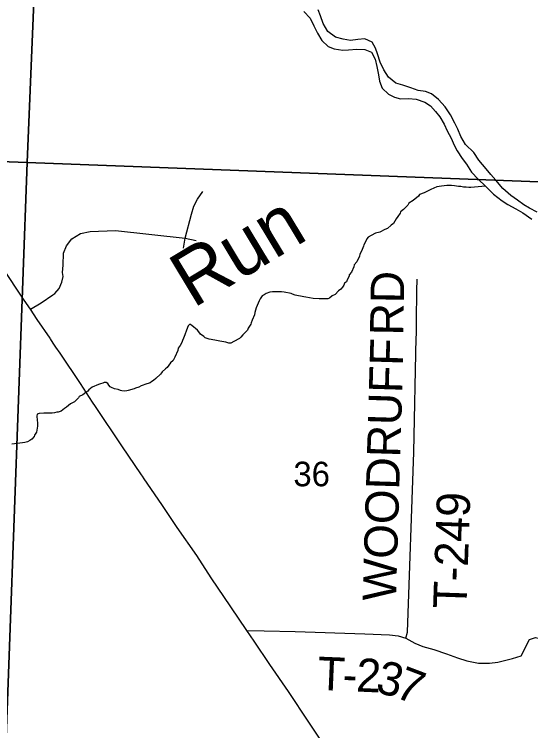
# Model space of a CAD drawing. Extents: x 0 to 34, y 0 to 22.
# Drawn here: x 5.004 to 5.884, y 17.741 to 18.962 of the extents above; entities that cross this region are included whole.
import ezdxf

# ---------------------------------------------------------------- set-up
doc = ezdxf.new("R2010")
doc.units = 0
for name, color, linetype in [('GM_X_Major_River', 7, 'Continuous'), ('GM_X_Minor_River', 7, 'Continuous'), ('GM_X_Minor_River_Text', 7, 'Continuous'), ('GM_X_Section', 7, 'Continuous'), ('GM_X_Section_Text', 7, 'Continuous'), ('GM_X_Township_Road', 7, 'Continuous'), ('GM_X_Township_Road_Text', 7, 'Continuous'), ('GM_X_US_Route', 7, 'Continuous')]:
    doc.layers.add(name, color=color, linetype=linetype)

msp = doc.modelspace()

# ---------------------------------------------------------------- linework, layer by layer
at = {"layer": 'GM_X_Major_River'}
for points in [[(5.4975, 18.9668), (5.5083, 18.9552), (5.5146, 18.9422), (5.5208, 18.9295), (5.5281, 18.9173), (5.5393, 18.9068), (5.5495, 18.9028), (5.5643, 18.901), (5.5738, 18.9013), (5.5882, 18.9025), (5.6015, 18.9019), (5.6132, 18.8971), (5.619, 18.8857), (5.6222, 18.8727), (5.625, 18.8586), (5.6267, 18.8479), (5.6314, 18.8361), (5.6422, 18.826), (5.652, 18.8205), (5.6622, 18.8177), (5.6762, 18.8182), (5.6891, 18.8172), (5.7038, 18.8124), (5.7136, 18.8061), (5.7221, 18.7965), (5.7295, 18.7869), (5.7369, 18.7746), (5.742, 18.7631), (5.7486, 18.7508), (5.7541, 18.7389), (5.7588, 18.729), (5.7673, 18.7159), (5.7747, 18.7063), (5.7832, 18.6929), (5.7948, 18.6809), (5.8071, 18.6689), (5.8209, 18.6554), (5.8355, 18.6441), (5.8452, 18.6378), (5.8587, 18.6304), (5.8711, 18.6237), (5.8865, 18.6128)], [(5.8951, 18.6244), (5.8823, 18.6315), (5.8725, 18.637), (5.862, 18.6451), (5.8504, 18.6529), (5.837, 18.6649), (5.8251, 18.6792), (5.8165, 18.6889), (5.8084, 18.6985), (5.7961, 18.7131), (5.7876, 18.7262), (5.7731, 18.7398), (5.7654, 18.7536), (5.7599, 18.7662), (5.7552, 18.7765), (5.7478, 18.7907), (5.7386, 18.8042), (5.727, 18.8165), (5.7151, 18.8266), (5.7053, 18.8306), (5.6924, 18.8323), (5.68, 18.8363), (5.6664, 18.8411), (5.6543, 18.8444), (5.642, 18.8545), (5.6339, 18.8675), (5.6277, 18.8806), (5.623, 18.8947), (5.6197, 18.9042), (5.6139, 18.9146), (5.6018, 18.9198), (5.5896, 18.9188), (5.5771, 18.9175), (5.5646, 18.9197), (5.5514, 18.9229), (5.5387, 18.9326), (5.5309, 18.9464), (5.5259, 18.9595), (5.5219, 18.9694)]]:
    msp.add_lwpolyline(points, dxfattribs=at)
at = {"layer": 'GM_X_Minor_River'}
for points in [[(5.8071, 18.6689), (5.7821, 18.6668), (5.7786, 18.6669), (5.7741, 18.6673), (5.7699, 18.6675), (5.7654, 18.6683), (5.7612, 18.6684), (5.7544, 18.6694), (5.7491, 18.6702), (5.7411, 18.6704), (5.7323, 18.6688), (5.7243, 18.6678), (5.7143, 18.6635), (5.7105, 18.6617), (5.7028, 18.6577), (5.6947, 18.6545), (5.6931, 18.6519), (5.6842, 18.6445), (5.6765, 18.6401), (5.6749, 18.6368), (5.6675, 18.629), (5.6624, 18.6253), (5.6616, 18.623), (5.6577, 18.6171), (5.6549, 18.6133), (5.6506, 18.6051), (5.6467, 18.6025), (5.6405, 18.597), (5.6355, 18.5952), (5.6274, 18.5905), (5.6201, 18.5888), (5.6125, 18.5851), (5.6074, 18.5819), (5.6051, 18.5793), (5.6023, 18.5729), (5.5999, 18.5691), (5.5995, 18.5665), (5.5962, 18.5582), (5.5931, 18.5533), (5.5926, 18.5499), (5.5882, 18.5402), (5.5835, 18.535), (5.5831, 18.5316), (5.5787, 18.5226), (5.5752, 18.5181), (5.5747, 18.5158), (5.5715, 18.5094), (5.5703, 18.5061), (5.5672, 18.5035), (5.5656, 18.5001), (5.5636, 18.4971), (5.5609, 18.4934), (5.5566, 18.4904), (5.5508, 18.4841), (5.5462, 18.482), (5.5415, 18.4779), (5.5385, 18.4772), (5.5335, 18.477), (5.5236, 18.4768), (5.5134, 18.4775), (5.5012, 18.4797), (5.4978, 18.4801), (5.4831, 18.4835), (5.4786, 18.4852), (5.4759, 18.486), (5.4642, 18.4882), (5.4596, 18.4887), (5.4444, 18.4891), (5.4395, 18.4884), (5.4337, 18.4863), (5.4298, 18.4837), (5.4268, 18.4823), (5.4232, 18.4767), (5.4216, 18.4737), (5.4164, 18.4616), (5.4143, 18.4537), (5.4135, 18.4496), (5.4095, 18.4405), (5.4082, 18.436), (5.4074, 18.4338), (5.4031, 18.427), (5.4014, 18.4233), (5.3937, 18.4155), (5.3905, 18.4118), (5.3882, 18.4092), (5.3786, 18.4045), (5.3732, 18.4016), (5.3701, 18.4016), (5.3645, 18.4029), (5.3546, 18.4051), (5.3459, 18.4064), (5.3364, 18.4082), (5.3296, 18.4103), (5.3274, 18.4126), (5.3218, 18.4169), (5.3189, 18.4208), (5.3166, 18.4235), (5.3066, 18.4313), (5.3032, 18.4337), (5.3005, 18.4307), (5.298, 18.4236)], [(5.298, 18.4236), (5.2948, 18.4157), (5.2924, 18.4097), (5.2911, 18.4059), (5.2895, 18.4025), (5.2868, 18.3976), (5.2836, 18.3928), (5.2831, 18.389), (5.2776, 18.3777), (5.2748, 18.3717), (5.2705, 18.368), (5.2646, 18.3598), (5.2619, 18.3576), (5.2564, 18.3528), (5.2549, 18.3506), (5.2537, 18.3483), (5.2455, 18.3413), (5.2416, 18.3376), (5.2389, 18.3358), (5.2358, 18.3336), (5.2266, 18.3308), (5.224, 18.3297), (5.2205, 18.3286), (5.2163, 18.3265), (5.2109, 18.3247), (5.2086, 18.3236), (5.1983, 18.3208), (5.196, 18.3201), (5.1914, 18.3195), (5.1876, 18.32), (5.185, 18.3208), (5.1812, 18.3224), (5.1751, 18.3237), (5.1699, 18.3257), (5.1676, 18.3269), (5.1654, 18.33), (5.1636, 18.3327), (5.1609, 18.3343), (5.1575, 18.3344), (5.1552, 18.3333), (5.1514, 18.3319), (5.1479, 18.3308), (5.1372, 18.3265), (5.131, 18.3221), (5.1294, 18.3195), (5.1263, 18.3173), (5.1213, 18.3136), (5.1147, 18.3104), (5.1136, 18.3081), (5.1066, 18.3015), (5.1, 18.2982), (5.0934, 18.2923), (5.0899, 18.2901), (5.0872, 18.2879), (5.0841, 18.2853), (5.0791, 18.2839), (5.0765, 18.2836), (5.073, 18.2826), (5.0688, 18.2823), (5.0662, 18.2823), (5.0612, 18.2821), (5.0548, 18.2823), (5.0464, 18.2813), (5.0433, 18.2806), (5.0429, 18.2769), (5.0431, 18.27), (5.0437, 18.2654), (5.0437, 18.2628), (5.044, 18.2601), (5.0435, 18.2567), (5.0422, 18.2499), (5.0387, 18.2447), (5.0379, 18.2424), (5.0343, 18.2376), (5.0309, 18.2354), (5.0266, 18.2332), (5.022, 18.2322), (5.0182, 18.2315), (5.0094, 18.2302), (5.0003, 18.2293)]]:
    msp.add_lwpolyline(points, dxfattribs=at)
at = {"layer": 'GM_X_Section'}
for points in [[(4.0623, 19.7415), (5.0674, 19.7096), (5.0264, 18.7096), (4.0218, 18.7461)], [(6.0653, 19.7127), (6.0336, 18.6715), (5.0264, 18.7096), (5.0674, 19.7096)], [(4.0218, 18.7461), (5.0264, 18.7096), (4.989, 17.6982), (3.996, 17.7284)], [(5.0264, 18.7096), (6.0336, 18.6715), (5.9983, 17.6719), (4.989, 17.6982)]]:
    msp.add_lwpolyline(points, close=True, dxfattribs=at)
at = {"layer": 'GM_X_Township_Road'}
msp.add_line((5.6905, 18.4907), (5.6908, 18.5106), dxfattribs=at)
for points in [[(5.2924, 18.5636), (5.2952, 18.5803), (5.3062, 18.6215), (5.3105, 18.635), (5.3162, 18.6471), (5.3258, 18.6599)], [(5.0702, 18.4839), (5.0731, 18.486), (5.0805, 18.4943), (5.0851, 18.5053), (5.0876, 18.5149), (5.0865, 18.522), (5.0876, 18.5344), (5.0883, 18.5547), (5.093, 18.5675), (5.1025, 18.5792), (5.1168, 18.5881), (5.1338, 18.5916), (5.1768, 18.5934), (5.2952, 18.5803), (5.314, 18.5764)], [(5.0318, 18.4591), (5.0503, 18.47), (5.0702, 18.4839)], [(5.6894, 18.4113), (5.6895, 18.4163), (5.6898, 18.4392), (5.6905, 18.4907)], [(5.6715, 17.8987), (5.6746, 17.909), (5.685, 18.2157), (5.6894, 18.4113)], [(5.4006, 17.9118), (5.4302, 17.9111), (5.4827, 17.91), (5.6015, 17.9059), (5.6437, 17.9043), (5.6586, 17.9024), (5.6715, 17.8987)], [(5.6715, 17.8987), (5.6867, 17.8903), (5.7006, 17.8844), (5.719, 17.8791), (5.7406, 17.8719), (5.7595, 17.8653), (5.7756, 17.86), (5.7955, 17.8558), (5.8142, 17.8558), (5.8282, 17.8575), (5.8535, 17.8642), (5.8683, 17.8685), (5.8823, 17.8966), (5.8923, 17.8997), (5.9051, 17.897), (5.9116, 17.8979), (5.9328, 17.9048), (5.9604, 17.9115)]]:
    msp.add_lwpolyline(points, dxfattribs=at)
at = {"layer": 'GM_X_US_Route'}
msp.add_line((5.2211, 18.1772), (5.1878, 18.2266), dxfattribs=at)
for points in [[(5.0213, 18.4746), (5.0109, 18.4902), (4.9931, 18.5166), (4.9903, 18.521), (4.9869, 18.5261), (4.977, 18.5393), (4.964, 18.5595), (4.9489, 18.5828), (4.9383, 18.5988), (4.9201, 18.6265), (4.9162, 18.6326), (4.8916, 18.6707), (4.8723, 18.7009), (4.8694, 18.7052)], [(5.0652, 18.4097), (5.0435, 18.4415), (5.0318, 18.4591), (5.0213, 18.4746)], [(5.0707, 18.4014), (5.0657, 18.4088), (5.0652, 18.4097)], [(5.1378, 18.3009), (5.1168, 18.3326), (5.0822, 18.3842), (5.0751, 18.3947), (5.0707, 18.4014)], [(5.1878, 18.2266), (5.1428, 18.2934), (5.1378, 18.3009)], [(5.5535, 17.6844), (5.5416, 17.7031), (5.534, 17.714), (5.5233, 17.7302), (5.5061, 17.7554), (5.4715, 17.8075), (5.44, 17.8535), (5.4133, 17.8934), (5.4006, 17.9118), (5.3731, 17.9519), (5.3399, 18.0013), (5.3154, 18.0393), (5.282, 18.0871), (5.2557, 18.1266), (5.2258, 18.1701), (5.2228, 18.1747), (5.2211, 18.1772)]]:
    msp.add_lwpolyline(points, dxfattribs=at)

# ---------------------------------------------------------------- texts
at = {"layer": 'GM_X_Minor_River_Text'}
msp.add_text('Run', height=0.09469, rotation=31.1038, dxfattribs=at).set_placement((5.3088, 18.46))
at = {"layer": 'GM_X_Section_Text'}
msp.add_text('36', height=0.04186, rotation=0, dxfattribs=at).set_placement((5.4799, 18.1575))
at = {"layer": 'GM_X_Township_Road_Text'}
for s, height, rotation, p in [('RD', 0.05682, 89.0062, (5.6671, 18.4142)), ('WOODRUFF', 0.05682, 88.2937, (5.6546, 17.9615)), ('T-249', 0.05682, 88.0347, (5.7747, 17.9482)), ('T', 0.0568, 357.5993, (5.5203, 17.8105)), ('2', 0.0568, 357.5378, (5.5861, 17.8078)), ('3', 0.0568, 346.3244, (5.6181, 17.8067)), ('7', 0.0568, 339.2766, (5.6504, 17.799)), ('-', 0.0568, 357.5872, (5.5628, 17.8088))]:
    msp.add_text(s, height=height, rotation=rotation, dxfattribs=at).set_placement(p)

doc.saveas('drawing.dxf')
